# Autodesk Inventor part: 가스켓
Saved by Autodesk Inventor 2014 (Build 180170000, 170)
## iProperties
Created: 2024-05
Part Number: 가스켓
Material: 일반
Document SubType Name: Modeling
Designer: dg
Density: 1 g/cm^3
Appearance: 기본값
Author: dg
Author: jhkim
Creation Date: 2024-05-07
Sending System: Autodesk Inventor 2025
Preprocessor: ST-DEVELOPER v20
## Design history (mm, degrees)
node "가스켓1"
node "솔리드1"
node "기준1"
